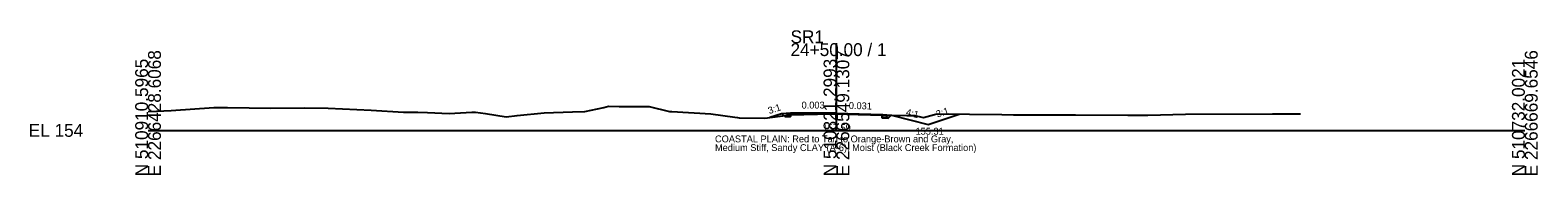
# Model space of a CAD drawing. Extents: x -1079 to 303, y -11 to 4017.
# Drawn here: x -25.7 to 302.8, y 3490.3 to 3521.8 of the extents above; entities that cross this region are included whole.
import ezdxf

# ---------------------------------------------------------------- set-up
doc = ezdxf.new("R2010")
doc.units = 0
for name, color, linetype in [('Default', 7, 'Continuous'), ('Exist Cross Section Cell', 7, 'Continuous'), ('Exist XS Center Line Elevation Label', 7, 'Continuous'), ('Exist XS Ground Line', 7, 'Continuous'), ('Prop CMT Pvmt Course 1', 7, 'Continuous'), ('Prop CMT Pvmt Course 2', 7, 'Continuous'), ('Prop CMT Pvmt Course 3', 7, 'Continuous'), ('Prop CMT Pvmt Surface', 7, 'Continuous'), ('Prop CMT Pvmt Surface Shoulder', 7, 'Continuous'), ('Prop CMT Shld Paved Course 1', 7, 'Continuous'), ('Prop CMT Shld Paved Course 2', 7, 'Continuous'), ('Prop CMT Shld Paved Course 3', 7, 'Continuous'), ('Prop CMT Slope Grass', 7, 'Continuous'), ('Prop CMT Subgrade Earthwork', 7, 'Continuous'), ('Prop Road Sect_ Material - Tx (Composite Desc)', 7, 'Continuous'), ('Prop XS Ditch Standard Text', 7, 'Continuous'), ('Prop XS SE Text', 7, 'Continuous'), ('Prop XS Side Slope Text', 7, 'Continuous')]:
    doc.layers.add(name, color=color, linetype=linetype)

msp = doc.modelspace()

# ---------------------------------------------------------------- linework, layer by layer
at = {"layer": 'Exist Cross Section Cell'}
for p, q in [((150, 3500), (150, 3519)), ((0, 3500), (150, 3500)), ((150, 3500), (300, 3500))]:
    msp.add_line(p, q, dxfattribs=at)
at = {"layer": 'Exist XS Ground Line'}
msp.add_lwpolyline([(0, 3504.14), (1.86, 3504.2), (5.04, 3504.31), (14.31, 3504.99), (17.28, 3504.97), (26.76, 3504.81), (34.08, 3504.89), (39.21, 3504.83), (48.63, 3504.37), (55.67, 3503.97), (57.09, 3503.97), (58.76, 3503.98), (60.9, 3503.89), (65.61, 3503.69), (70.55, 3503.94), (71.32, 3504), (73.56, 3503.66), (78.06, 3502.94), (80.4, 3503.25), (86.29, 3503.85), (92.51, 3504.03), (95.15, 3504.09), (99.3, 3505.02), (100.31, 3505.25), (102.68, 3505.24), (109.22, 3505.23), (113.64, 3504.15), (114.16, 3504.12), (122.64, 3503.6), (127.87, 3502.86), (128.45, 3502.78), (128.79, 3502.77), (134.42, 3502.64), (139.97, 3503.41), (145.9, 3503.53), (149.82, 3503.59), (154.76, 3503.48), (160.08, 3503.35), (165.34, 3503.25), (167.06, 3503.21), (168.58, 3502.9), (168.97, 3502.83), (171.34, 3503.47), (171.95, 3503.62), (186.02, 3503.45), (188.57, 3503.39), (197.97, 3503.39), (201.02, 3503.37), (201.47, 3503.37), (202.08, 3503.38), (213.47, 3503.33), (214.93, 3503.29), (217.87, 3503.33), (226.07, 3503.55), (245.03, 3503.64), (251.1, 3503.61)], dxfattribs=at)
at = {"layer": 'Prop CMT Pvmt Course 1'}
for points in [[(150, 3503.78), (140, 3503.75)], [(140, 3503.75), (140, 3503.5), (140, 3503.5), (140, 3503.62)], [(140, 3503.62), (150, 3503.65)], [(150, 3503.53), (150, 3503.78)], [(150, 3503.78), (160, 3503.47)], [(150, 3503.53), (150, 3503.78)], [(150, 3503.65), (150, 3503.53), (150, 3503.53)], [(160, 3503.34), (150, 3503.65)], [(150, 3503.65), (150, 3503.53), (150, 3503.53)], [(160, 3503.47), (160, 3503.22), (160, 3503.22), (160, 3503.34)]]:
    msp.add_lwpolyline(points, dxfattribs=at)
at = {"layer": 'Prop CMT Pvmt Course 2'}
for points in [[(140, 3503.5), (140, 3503.5), (140, 3503.5)], [(160, 3503.22), (160, 3503.22), (160, 3503.22)]]:
    msp.add_lwpolyline(points, close=True, dxfattribs=at)
for points in [[(140, 3503.5), (140, 3503.5)], [(160, 3503.22), (160, 3503.22)]]:
    msp.add_lwpolyline(points, dxfattribs=at)
at = {"layer": 'Prop CMT Pvmt Course 3'}
for points in [[(140, 3503.5), (140, 3503.5), (140, 3503), (140, 3503)], [(140, 3503), (140, 3503.5)], [(160, 3503.22), (160, 3503.22), (160, 3502.72), (160, 3502.72)], [(160, 3502.72), (160, 3503.22)]]:
    msp.add_lwpolyline(points, dxfattribs=at)
at = {"layer": 'Prop CMT Pvmt Surface'}
for q in [(140, 3503.75), (160, 3503.47)]:
    msp.add_line((150, 3503.78), q, dxfattribs=at)
at = {"layer": 'Prop CMT Pvmt Surface Shoulder'}
for p, q in [((140, 3503.75), (140, 3503.75)), ((160, 3503.47), (160, 3503.47))]:
    msp.add_line(p, q, dxfattribs=at)
at = {"layer": 'Prop CMT Shld Paved Course 1'}
for points in [[(140, 3503.75), (140, 3503.75), (139.75, 3503.5)], [(139.75, 3503.5), (140, 3503.5)], [(140, 3503.5), (140, 3503.75)], [(160, 3503.47), (160, 3503.47), (160.26, 3503.21)], [(160, 3503.22), (160, 3503.47)], [(160.26, 3503.21), (160, 3503.22)]]:
    msp.add_lwpolyline(points, dxfattribs=at)
at = {"layer": 'Prop CMT Shld Paved Course 2'}
for points in [[(140, 3503.5), (139.75, 3503.5)], [(139.75, 3503.5), (139.75, 3503.5)], [(139.75, 3503.5), (140, 3503.5)], [(140, 3503.5), (140, 3503.5)], [(160, 3503.22), (160.26, 3503.21)], [(160.26, 3503.21), (160, 3503.22)], [(160, 3503.22), (160, 3503.22)], [(160.26, 3503.21), (160.26, 3503.21)]]:
    msp.add_lwpolyline(points, dxfattribs=at)
at = {"layer": 'Prop CMT Shld Paved Course 3'}
for points in [[(140, 3503.5), (139.75, 3503.5), (139.25, 3503.49), (138.75, 3502.99)], [(138.75, 3502.99), (140, 3503)], [(140, 3503), (140, 3503.5)], [(160, 3503.22), (160.26, 3503.21), (160.76, 3503.19), (161.28, 3502.68)], [(160, 3502.72), (160, 3503.22)], [(161.28, 3502.68), (160, 3502.72)]]:
    msp.add_lwpolyline(points, dxfattribs=at)
at = {"layer": 'Prop CMT Slope Grass'}
for p, q in [((138, 3503.62), (135.5, 3502.79)), ((140, 3503.75), (138, 3503.62)), ((160, 3503.47), (162, 3503.31)), ((162, 3503.31), (170, 3501.31)), ((170, 3501.31), (176.76, 3503.56))]:
    msp.add_line(p, q, dxfattribs=at)
at = {"layer": 'Prop CMT Subgrade Earthwork'}
for points in [[(138.75, 3502.99), (138.11, 3503.63)], [(140, 3503), (138.75, 3502.99)], [(140, 3503), (140, 3503.42)], [(140, 3503), (140, 3503)], [(160, 3502.72), (160, 3503.36)], [(160, 3502.72), (161.28, 3502.68)], [(160, 3502.72), (160, 3502.72)], [(161.28, 3502.68), (161.91, 3503.31)]]:
    msp.add_lwpolyline(points, dxfattribs=at)

# ---------------------------------------------------------------- texts
at = {"layer": 'Default'}
msp.add_text('-', height=0.0001, dxfattribs=at).set_placement((0, 3500))
at = {"layer": 'Exist Cross Section Cell'}
for s, p in [('SR1', (140, 3519)), ('24+50.00 / 1', (140, 3516.2)), ('EL 154', (-26, 3498.6))]:
    msp.add_text(s, height=2.8, dxfattribs=at).set_placement(p)
for s, p in [('N 510910.5965', (0, 3490)), ('E 2266428.6068', (2.8, 3490)), ('N 510821.2993', (150, 3490)), ('E 2266549.1307', (152.8, 3490)), ('N 510732.0021', (300, 3490)), ('E 2266669.6546', (302.8, 3490))]:
    msp.add_text(s, height=2.8, rotation=90, dxfattribs=at).set_placement(p)
at = {"layer": 'Exist XS Center Line Elevation Label'}
msp.add_text('157.59', height=1.5, dxfattribs=at).set_placement((146.98, 3499.84))
at = {"layer": 'Prop Road Sect_ Material - Tx (Composite Desc)'}
for s, p in [('COASTAL PLAIN: Red to Tan to Orange-Brown and Gray, ', (123.54, 3497.39)), ('Medium Stiff, Sandy CLAY (A-6), Moist (Black Creek Formation)', (123.54, 3495.49))]:
    msp.add_text(s, height=1.5, dxfattribs=at).set_placement(p)
at = {"layer": 'Prop XS Ditch Standard Text'}
msp.add_text('155.31', height=1.5, dxfattribs=at).set_placement((167.24, 3499.06))
at = {"layer": 'Prop XS SE Text'}
for s, rotation, p in [('0.003', 0.1776, (142.41, 3504.75)), ('0.031', 358.213, (152.68, 3504.69))]:
    msp.add_text(s, height=1.5, rotation=rotation, dxfattribs=at).set_placement(p)
at = {"layer": 'Prop XS Side Slope Text'}
for s, rotation, p in [('3:1', 18.4332, (135.38, 3503.54)), ('4:1', 345.9638, (165.03, 3503.32)), ('3:1', 18.4332, (172.01, 3502.77))]:
    msp.add_text(s, height=1.5, rotation=rotation, dxfattribs=at).set_placement(p)

doc.saveas('drawing.dxf')
